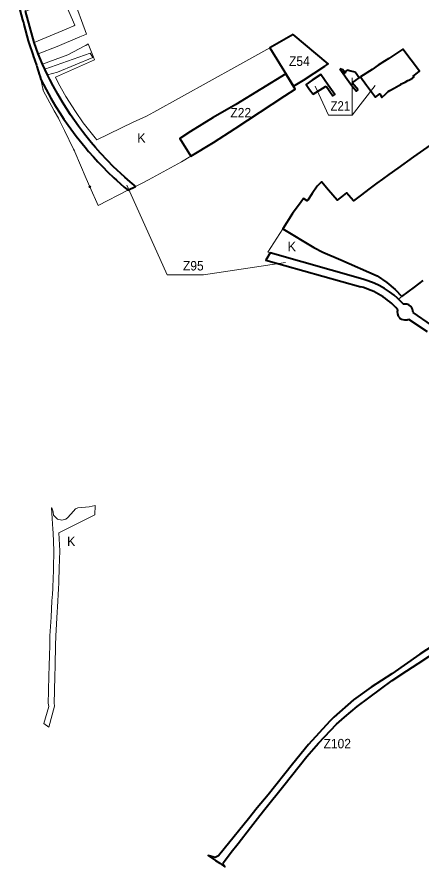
# Model space of a CAD drawing. Extents: x -650276 to -642489, y -1074311 to -1066658.
# Drawn here: x -649069 to -648043, y -1072846 to -1070690 of the extents above; entities that cross this region are included whole.
import ezdxf

# ---------------------------------------------------------------- set-up
doc = ezdxf.new("R2010")
doc.units = 0
doc.header["$LTSCALE"] = 9.6
doc.header["$PDMODE"] = 32
doc.header["$PDSIZE"] = 4.8
for name, color, linetype, lineweight in [('42', 7, 'Continuous', 25), ('44', 7, 'Continuous', 40), ('45', 7, 'Continuous', 40), ('46', 7, 'Continuous', 13), ('47', 7, 'Continuous', 13), ('48', 7, 'Continuous', 13)]:
    doc.layers.add(name, color=color, linetype=linetype, lineweight=lineweight)

msp = doc.modelspace()

# ---------------------------------------------------------------- linework, layer by layer
at = {"layer": '42'}
msp.add_lwpolyline([(-648386.587, -1070833.807), (-648512.981, -1070911.776), (-648571.14, -1070944.67), (-648628.712, -1070979.892), (-648655.76, -1070997.5), (-648627.39, -1071042.65), (-648570.23, -1071008.2), (-648515.46, -1070972.94), (-648389.33, -1070889.79), (-648362.519, -1070872.788)], close=True, dxfattribs=at)
at = {"layer": '44'}
for points in [[(-649068.65, -1070642.23), (-649054.31, -1070696.44), (-649052.77, -1070702.25), (-649052.44, -1070703.48), (-649051.03, -1070708.74), (-649040.03, -1070750.06), (-649039.38, -1070752.51), (-649039.06, -1070753.72), (-649038.51, -1070755.38), (-649027.74, -1070787.51), (-649027.64, -1070787.8), (-649019.48, -1070812.18), (-649018.48, -1070815.18), (-649011.24, -1070836.79), (-649010.67, -1070838.5), (-649007.885, -1070848.153), (-648994.464, -1070873.974), (-648982.467, -1070895.704), (-648970.712, -1070915.663), (-648960.268, -1070932.429), (-648949.389, -1070949.031), (-648939.232, -1070963.818), (-648918.601, -1070991.969), (-648896.068, -1071020.184), (-648886.874, -1071031.044), (-648874.793, -1071044.773), (-648863.847, -1071056.723), (-648851.175, -1071069.886), (-648838.696, -1071082.562), (-648823.087, -1071097.562), (-648816.379, -1071103.782), (-648806.239, -1071112.938), (-648797, -1071121), (-648790.23, -1071126.818), (-648787.207, -1071129.363), (-648767.824, -1071119.455), (-648771.725, -1071116.233), (-648781.806, -1071107.721), (-648795.407, -1071095.8), (-648824.292, -1071068.677), (-648839.273, -1071053.556), (-648856.883, -1071034.761), (-648869.629, -1071020.411), (-648880.44, -1071007.703), (-648894.164, -1070990.806), (-648902.714, -1070979.812), (-648912.396, -1070966.893), (-648922.92, -1070952.242), (-648932.78, -1070937.887), (-648943.414, -1070921.659), (-648953.605, -1070905.299), (-648965.093, -1070885.794), (-648976.834, -1070864.527), (-648985.145, -1070848.538), (-648991.386, -1070835.954), (-648998.132, -1070821.723), (-649003.641, -1070809.566), (-649014.888, -1070782.994), (-649025.129, -1070754.377), (-649047.11, -1070674.743)], [(-648079.109, -1071418.563), (-648082.391, -1071418.063), (-648085.477, -1071418.086), (-648087.928, -1071418.446), (-648100.438, -1071405.517), (-648103.268, -1071402.88), (-648111.646, -1071395.618), (-648123.313, -1071386.696), (-648136.263, -1071378.194), (-648149.571, -1071370.788), (-648162.084, -1071364.918), (-648178.158, -1071358.781), (-648191.25, -1071354.858), (-648426.18, -1071288.32), (-648437.454, -1071306.778), (-648196.236, -1071374.226)], [(-648069.022, -1071424.443), (-648074.341, -1071420.189), (-648079.108, -1071418.564), (-648079.109, -1071418.563)], [(-648063.593, -1071439.723), (-648063.862, -1071435.078), (-648064.838, -1071431.28), (-648066.623, -1071427.592), (-648069.022, -1071424.443)], [(-648103.894, -1071436.836), (-648103.478, -1071442.736), (-648101.203, -1071448.31)], [(-648016.446, -1071471.268), (-648063.593, -1071439.723)], [(-648101.203, -1071448.31), (-648098.259, -1071452.196), (-648096.014, -1071454.192), (-648093.059, -1071456.066), (-648089.539, -1071457.489), (-648085.585, -1071458.248), (-648081.642, -1071458.215), (-648078.539, -1071457.636), (-648074.86, -1071456.248)], [(-648074.86, -1071456.248), (-648027.562, -1071487.894)], [(-647942.21, -1072238.54), (-648046.69, -1072306.3), (-648117.12, -1072356), (-648169.81, -1072390.035), (-648214.73, -1072422.41), (-648264.618, -1072466.244), (-648274.53, -1072476.196), (-648328.847, -1072535.816), (-648369.37, -1072585.645), (-648431.557, -1072662.77), (-648459.243, -1072696.417), (-648481.468, -1072723.736), (-648543.255, -1072800.016), (-648557.588, -1072817.727), (-648565.726, -1072822.048), (-648583.407, -1072817.256), (-648564.86, -1072829.45), (-648554.22, -1072836.89), (-648541.102, -1072846.281), (-648545.462, -1072840.329), (-648544.632, -1072835.177), (-648524.979, -1072808.383), (-648507.503, -1072786.605), (-648476.204, -1072746.1), (-648452.274, -1072715.637), (-648439.912, -1072699.826), (-648391.796, -1072639.344), (-648333.178, -1072565.837), (-648303.791, -1072531.792), (-648258.165, -1072484.283), (-648237.406, -1072465.811), (-648205.298, -1072439.308), (-648116.32, -1072373.44), (-648079.76, -1072348.46), (-648050.276, -1072330.025), (-647969.894, -1072276.479)]]:
    msp.add_lwpolyline(points, dxfattribs=at)
at = {"layer": '44', "lineweight": 13}
msp.add_lwpolyline([(-648790.074, -1071116.496), (-648687.825, -1071343.817), (-648595.588, -1071343.817), (-648387.63, -1071312.498)], dxfattribs=at)
at = {"layer": '44'}
for centre, radius, start, end in [((-648244.965, -1071557.871), 190, 41.59858, 75.1393), ((-648083.781, -1071438.172), 20.157, 161.35794, 176.20098)]:
    msp.add_arc(centre, radius, start, end, dxfattribs=at)
at = {"layer": '45'}
msp.add_lwpolyline([(-648368.163, -1070734.376), (-648427.25, -1070767.95), (-648366.98, -1070865.44), (-648341.58, -1070849.98), (-648287.74, -1070814.32), (-648282.44, -1070810.84), (-648278.832, -1070808.761)], close=True, dxfattribs=at)
for points in [[(-648095.42, -1070860.3), (-648083.65, -1070854.89), (-648076.73, -1070851.07), (-648074.41, -1070849.79), (-648072.59, -1070848.79), (-648065.35, -1070844.8), (-648061.52, -1070842.68), (-648063.76, -1070839.49), (-648056.61, -1070834.26), (-648047.17, -1070827.35), (-648089.27, -1070771.57), (-648104.78, -1070781.65), (-648114.77, -1070788.08), (-648125.2, -1070794.79), (-648136.08, -1070801.79)], [(-648095.42, -1070860.3), (-648083.65, -1070854.89), (-648076.73, -1070851.07), (-648074.41, -1070849.79), (-648072.59, -1070848.79), (-648065.35, -1070844.8), (-648061.52, -1070842.68), (-648063.76, -1070839.49), (-648056.61, -1070834.26), (-648047.17, -1070827.35), (-648089.27, -1070771.57), (-648104.78, -1070781.65), (-648114.77, -1070788.08), (-648125.2, -1070794.79), (-648136.08, -1070801.79)], [(-648237.46, -1070829.68), (-648241.96, -1070823.46), (-648249.5, -1070821.08)], [(-648249.5, -1070821.08), (-648222.158, -1070859.221), (-648217.1, -1070865.56), (-648207.151, -1070878.029), (-648202.798, -1070874.754)], [(-648136.08, -1070801.79), (-648151.77, -1070812.11), (-648167.6, -1070822.53), (-648196.65, -1070841.7), (-648181.75, -1070862.74), (-648158.58, -1070892.98), (-648148.34, -1070884.92), (-648142.79, -1070893.78), (-648133.14, -1070884.6), (-648127, -1070878.75), (-648122.72, -1070876.44), (-648111.24, -1070870.11), (-648099.85, -1070863.82), (-648094.9, -1070861.09), (-648095.42, -1070860.3)], [(-648136.08, -1070801.79), (-648151.77, -1070812.11), (-648167.6, -1070822.53), (-648196.65, -1070841.7), (-648181.75, -1070862.74), (-648158.58, -1070892.98), (-648148.34, -1070884.92), (-648142.79, -1070893.78), (-648133.14, -1070884.6), (-648127, -1070878.75), (-648122.72, -1070876.44), (-648111.24, -1070870.11), (-648099.85, -1070863.82), (-648094.9, -1070861.09), (-648095.42, -1070860.3)], [(-648386.587, -1070833.807), (-648512.981, -1070911.776), (-648571.14, -1070944.67), (-648628.712, -1070979.892), (-648655.76, -1070997.5), (-648627.39, -1071042.65), (-648570.23, -1071008.2), (-648515.46, -1070972.94), (-648389.33, -1070889.79)], [(-648386.587, -1070833.807), (-648512.981, -1070911.776), (-648571.14, -1070944.67), (-648628.712, -1070979.892), (-648655.76, -1070997.5), (-648627.39, -1071042.65), (-648570.23, -1071008.2), (-648515.46, -1070972.94), (-648389.33, -1070889.79)], [(-648389.33, -1070889.79), (-648362.519, -1070872.788), (-648386.587, -1070833.807)], [(-648389.33, -1070889.79), (-648362.519, -1070872.788), (-648386.587, -1070833.807)], [(-648284.02, -1070864.91), (-648267.24, -1070889.9), (-648262.4, -1070886.58), (-648279.39, -1070862.98), (-648297.39, -1070835.36), (-648320.02, -1070850.16), (-648335.19, -1070860.49), (-648326.41, -1070873.55), (-648317.14, -1070885.48)], [(-648210.517, -1070829.445), (-648221.58, -1070827.03), (-648231.22, -1070824.92), (-648237.46, -1070829.68)], [(-648218.11, -1070856.44), (-648209.37, -1070850.44), (-648200.17, -1070844.094), (-648210.517, -1070829.445)], [(-648202.798, -1070874.754), (-648212.94, -1070862.74), (-648217.85, -1070856.93), (-648218.11, -1070856.44)], [(-648317.14, -1070885.48), (-648285.72, -1070865.96), (-648284.02, -1070864.91)], [(-647913.45, -1070940.79), (-648062.53, -1071044.59), (-648102.55, -1071072.86), (-648125.53, -1071089.51), (-648141.12, -1071100.71), (-648155.77, -1071111.23), (-648172.48, -1071123.95), (-648197.57, -1071143.03), (-648215.08, -1071156.35), (-648232.8, -1071135.6), (-648245.49, -1071145.91), (-648256.04, -1071154.5), (-648278.39, -1071128.74), (-648296.34, -1071108.04), (-648307.33, -1071118.47), (-648319.77, -1071137.52), (-648330.78, -1071154.36), (-648332.354, -1071156.279), (-648341.943, -1071150.071), (-648347.949, -1071158.385), (-648369.33, -1071188.149), (-648394.087, -1071227.18), (-648315.127, -1071274.052), (-648292.406, -1071286.112), (-648246.752, -1071306.054), (-648155.113, -1071346.082), (-648130, -1071363), (-648109, -1071381), (-648091.92, -1071399.07), (-648060.01, -1071374.69), (-648038.18, -1071358.51)]]:
    msp.add_lwpolyline(points, dxfattribs=at)
msp.add_point((-648237.46, -1070829.68), dxfattribs=at)
at = {"layer": '46'}
msp.add_line((-648217.945, -1070938.322), (-648217.945, -1070843.952), dxfattribs=at)
for points in [[(-648277.841, -1070938.322), (-648217.945, -1070938.322), (-648160.135, -1070863.066)], [(-648217.945, -1070938.322), (-648217.945, -1070938.322), (-648160.135, -1070863.066)], [(-648217.945, -1070938.322), (-648277.841, -1070938.322), (-648311.985, -1070865.23)]]:
    msp.add_lwpolyline(points, dxfattribs=at)
at = {"layer": '47'}
for p, q in [((-648883.73, -1071120.13), (-648862.97, -1071168.09)), ((-648862.97, -1071168.09), (-648787.207, -1071129.363)), ((-648191.25, -1071354.858), (-648178.158, -1071358.781))]:
    msp.add_line(p, q, dxfattribs=at)
for points in [[(-649014.888, -1070782.994), (-648966.35, -1070764.7), (-648908.94, -1070740.19), (-648892.215, -1070733.293), (-648927.2, -1070637.98), (-648941.064, -1070599.735), (-648965.569, -1070610.382), (-648956.687, -1070630.825), (-649050.081, -1070663.981), (-649047.11, -1070674.743), (-648952.455, -1070640.564), (-648922.196, -1070710.207), (-648924.668, -1070712.022), (-648943.837, -1070720.104), (-649025.129, -1070754.377)], [(-648988.248, -1072491.089), (-648973.238, -1072438.27), (-648974.424, -1072429.462), (-648973.655, -1072400.254), (-648972.605, -1072360.164), (-648972.025, -1072338.183), (-648971.955, -1072335.341), (-648970.605, -1072283.823), (-648970.001, -1072260.788), (-648967.285, -1072213.663), (-648964.865, -1072171.684), (-648963.895, -1072154.905), (-648963.052, -1072140.301), (-648962.27, -1072125.223), (-648962.165, -1072120.949), (-648961.355, -1072088.12), (-648960.263, -1072043.893), (-648962.195, -1071998.309), (-648871.27, -1071952.643), (-648870.458, -1071929.441), (-648885.56, -1071932.1), (-648914.45, -1071934.78), (-648919.79, -1071937.27), (-648925.64, -1071943.18), (-648939.51, -1071959.25), (-648944.69, -1071963.44), (-648955.25, -1071966.15), (-648966.01, -1071963.74), (-648975.65, -1071953.47), (-648976.85, -1071944.78), (-648979.85, -1071935.11), (-648980.94, -1071935.12), (-648977.48, -1071989.2), (-648976.91, -1071998.2), (-648975.27, -1072044.01), (-648976.35, -1072087.75), (-648977.16, -1072120.58), (-648977.26, -1072124.65), (-648977.3, -1072126.08), (-648977.33, -1072127.34), (-648978.03, -1072139.48), (-648978.87, -1072154.04), (-648979.84, -1072170.82), (-648982.26, -1072212.8), (-648984.99, -1072260.16), (-648985.6, -1072283.43), (-648986.31, -1072310.66), (-648986.95, -1072334.96), (-648987.02, -1072337.8), (-648987.6, -1072359.77), (-648988.65, -1072399.86), (-648989.45, -1072430.27), (-648988.27, -1072439.04), (-649000.851, -1072482.138)]]:
    msp.add_lwpolyline(points, close=True, dxfattribs=at)
for points in [[(-648971.041, -1070842.231), (-648872.375, -1070798.112), (-648874.87, -1070791.61), (-648887.84, -1070757.84), (-648894.08, -1070762.22), (-648896.11, -1070762.73), (-648939.5, -1070785.4), (-649003.641, -1070809.566), (-648998.132, -1070821.723), (-648882.919, -1070781.673), (-648876.64, -1070792.6), (-648965.475, -1070829.829), (-648991.386, -1070835.954)], [(-648386.587, -1070833.807), (-648427.25, -1070767.95), (-648511.09, -1070814.7), (-648721.54, -1070930.88), (-648740.25, -1070941.21), (-648774.23, -1070956.42), (-648866.341, -1071000.881)], [(-648991.386, -1070835.954), (-648985.145, -1070848.538), (-648976.834, -1070864.527), (-648965.093, -1070885.794), (-648953.605, -1070905.299), (-648943.414, -1070921.659), (-648932.78, -1070937.887), (-648922.92, -1070952.242), (-648912.396, -1070966.893), (-648902.714, -1070979.812), (-648894.164, -1070990.806), (-648880.44, -1071007.703), (-648869.629, -1071020.411), (-648856.883, -1071034.761), (-648839.273, -1071053.556), (-648824.292, -1071068.677)], [(-648866.341, -1071000.881), (-648870.479, -1070996.265), (-648900.337, -1070957.964), (-648920.293, -1070929.567), (-648944.376, -1070891.404), (-648963.107, -1070858.328), (-648971.041, -1070842.231)], [(-648571.14, -1070944.67), (-648512.981, -1070911.776), (-648386.587, -1070833.807)], [(-648787.207, -1071129.363), (-648790.23, -1071126.818), (-648797, -1071121), (-648806.239, -1071112.938), (-648816.379, -1071103.782), (-648823.087, -1071097.562), (-648838.696, -1071082.562), (-648851.175, -1071069.886), (-648863.847, -1071056.723), (-648874.793, -1071044.773), (-648886.874, -1071031.044), (-648896.068, -1071020.184), (-648918.601, -1070991.969), (-648939.232, -1070963.818), (-648949.389, -1070949.031), (-648960.268, -1070932.429), (-648970.712, -1070915.663), (-648982.467, -1070895.704), (-648994.464, -1070873.974), (-649007.885, -1070848.153), (-649003.1, -1070871.35), (-649002.82, -1070872.69), (-649002.62, -1070873.69), (-649002.15, -1070875.96), (-648974.4, -1070927.77), (-648963.5, -1070946.45), (-648959.92, -1070953.73), (-648948.29, -1070977.37), (-648924.92, -1071024.89), (-648922.98, -1071029.49), (-648921.87, -1071032.04), (-648892.82, -1071099.15), (-648883.73, -1071120.13)], [(-648752.967, -1071111.861), (-648734.849, -1071102.599), (-648651.375, -1071057.109), (-648627.39, -1071042.65), (-648655.76, -1070997.5), (-648634.07, -1070983.17), (-648628.712, -1070979.892), (-648571.153, -1070944.678), (-648571.14, -1070944.67)], [(-648824.292, -1071068.677), (-648795.407, -1071095.8), (-648781.806, -1071107.721), (-648771.725, -1071116.233), (-648767.824, -1071119.455), (-648752.967, -1071111.861)], [(-648130, -1071363), (-648155.113, -1071346.082), (-648246.752, -1071306.054), (-648292.406, -1071286.112), (-648315.127, -1071274.052), (-648394.104, -1071227.17), (-648432.093, -1071286.645), (-648426.18, -1071288.32), (-648191.25, -1071354.858)], [(-648178.158, -1071358.781), (-648178.158, -1071358.781), (-648162.084, -1071364.918)], [(-648162.084, -1071364.918), (-648149.571, -1071370.788), (-648136.263, -1071378.194)], [(-648136.263, -1071378.194), (-648136.263, -1071378.194), (-648123.313, -1071386.696), (-648111.646, -1071395.618), (-648103.268, -1071402.88), (-648100.438, -1071405.517), (-648091.92, -1071399.07), (-648109, -1071381), (-648130, -1071363)]]:
    msp.add_lwpolyline(points, dxfattribs=at)
msp.add_point((-648883.73, -1071120.13), dxfattribs=at)

# ---------------------------------------------------------------- texts
at = {"layer": '44', "width": 0.95}
for s, p in [('Z95', (-648647.497, -1071332.741)), ('Z102', (-648290.724, -1072545.186))]:
    msp.add_text(s, height=24, dxfattribs=at).set_placement(p)
at = {"layer": '46'}
for s, width, p in [('Z54', 0.95, (-648378.37, -1070813.706)), ('Z21', 0.9, (-648272.998, -1070927.282)), ('Z22', 0.95, (-648527.125, -1070944.357)), ('Z22', 0.95, (-648527.125, -1070944.357))]:
    msp.add_text(s, height=24, dxfattribs=dict(at, width=width)).set_placement(p)
at = {"layer": '48'}
for p in [(-648763.558, -1071008.525), (-648763.558, -1071008.525), (-648382.039, -1071284.028), (-648941.849, -1072032.089), (-648941.849, -1072032.089)]:
    msp.add_text('K', height=24, dxfattribs=at).set_placement(p)

doc.saveas('drawing.dxf')
